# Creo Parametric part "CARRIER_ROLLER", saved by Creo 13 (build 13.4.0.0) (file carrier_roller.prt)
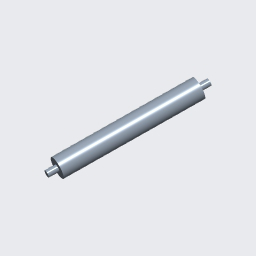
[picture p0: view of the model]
Units: millimeter Newton Second (mmNs); MM, TONNE, SECS

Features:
  1. datum plane "RIGHT"
  2. datum plane "TOP"
  3. datum plane "FRONT"
  4. coordinate system
  5. protrusion
  6. protrusion
  7. protrusion

Surfaces: 4 plane, 3 cylinder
